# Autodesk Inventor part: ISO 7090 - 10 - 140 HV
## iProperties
Created: 2001-08
Part Number: ISO 7090 - 10 - 140 HV
Catalog Web Link: file:///D:/Program%20Files/Autodesk/Inventor%205/Content/Iso/index.htm?doNavigateId=2A71B2AD-F337-496A-BFDA-377136DC7EA2|A6A69B3C91004B1B8DBEC0B273FB1932|true
Description: Washer
Document SubType Name: Standard Catalog Part
Standard: ISO 7090 - 10 - 140 HV
Designer: Martin Budgell
Control State: 0
Master: False
Checked Out: False
Length Units: 11269
Angle Units: 11279
Time Units: 11290
Mass Units: 11283
Shininess: 3
Angle Display Precision: 2
Document Length Units: 11269
Document Angle Units: 11279
Document Time Units: 11290
Document Mass Units: 11283
Document Length Units Precision: 3
Document Angle Units Precision: 2
Compacted: True
CLASSIFICATION: 31161807 un/spsc
MANUFACTURER: ISO Standard System
Density: 0.0
Volumn: 0.0
Area: 0.0
PropertySet Name: Model Information
Author: Martin Budgell
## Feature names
1. Base1
